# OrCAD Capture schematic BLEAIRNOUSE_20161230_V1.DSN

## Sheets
1 4:BLE_RF: size A
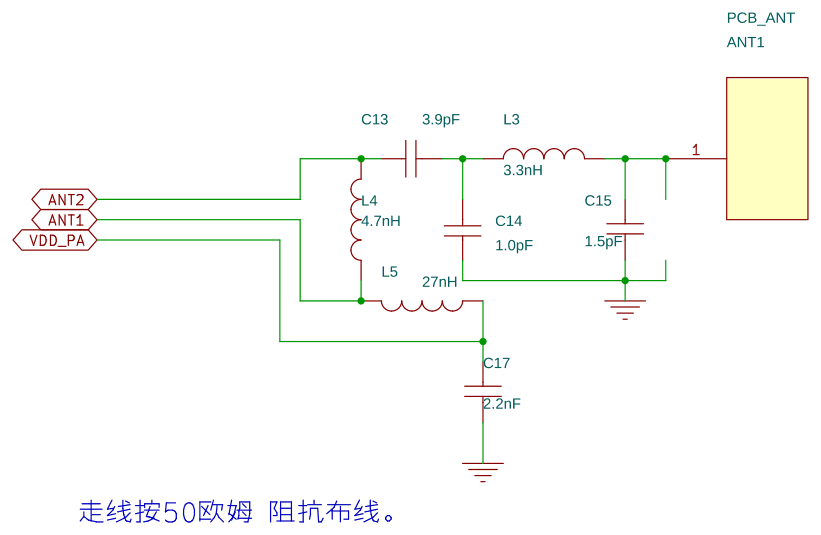
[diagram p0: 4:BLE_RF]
2 3:MISC: size A
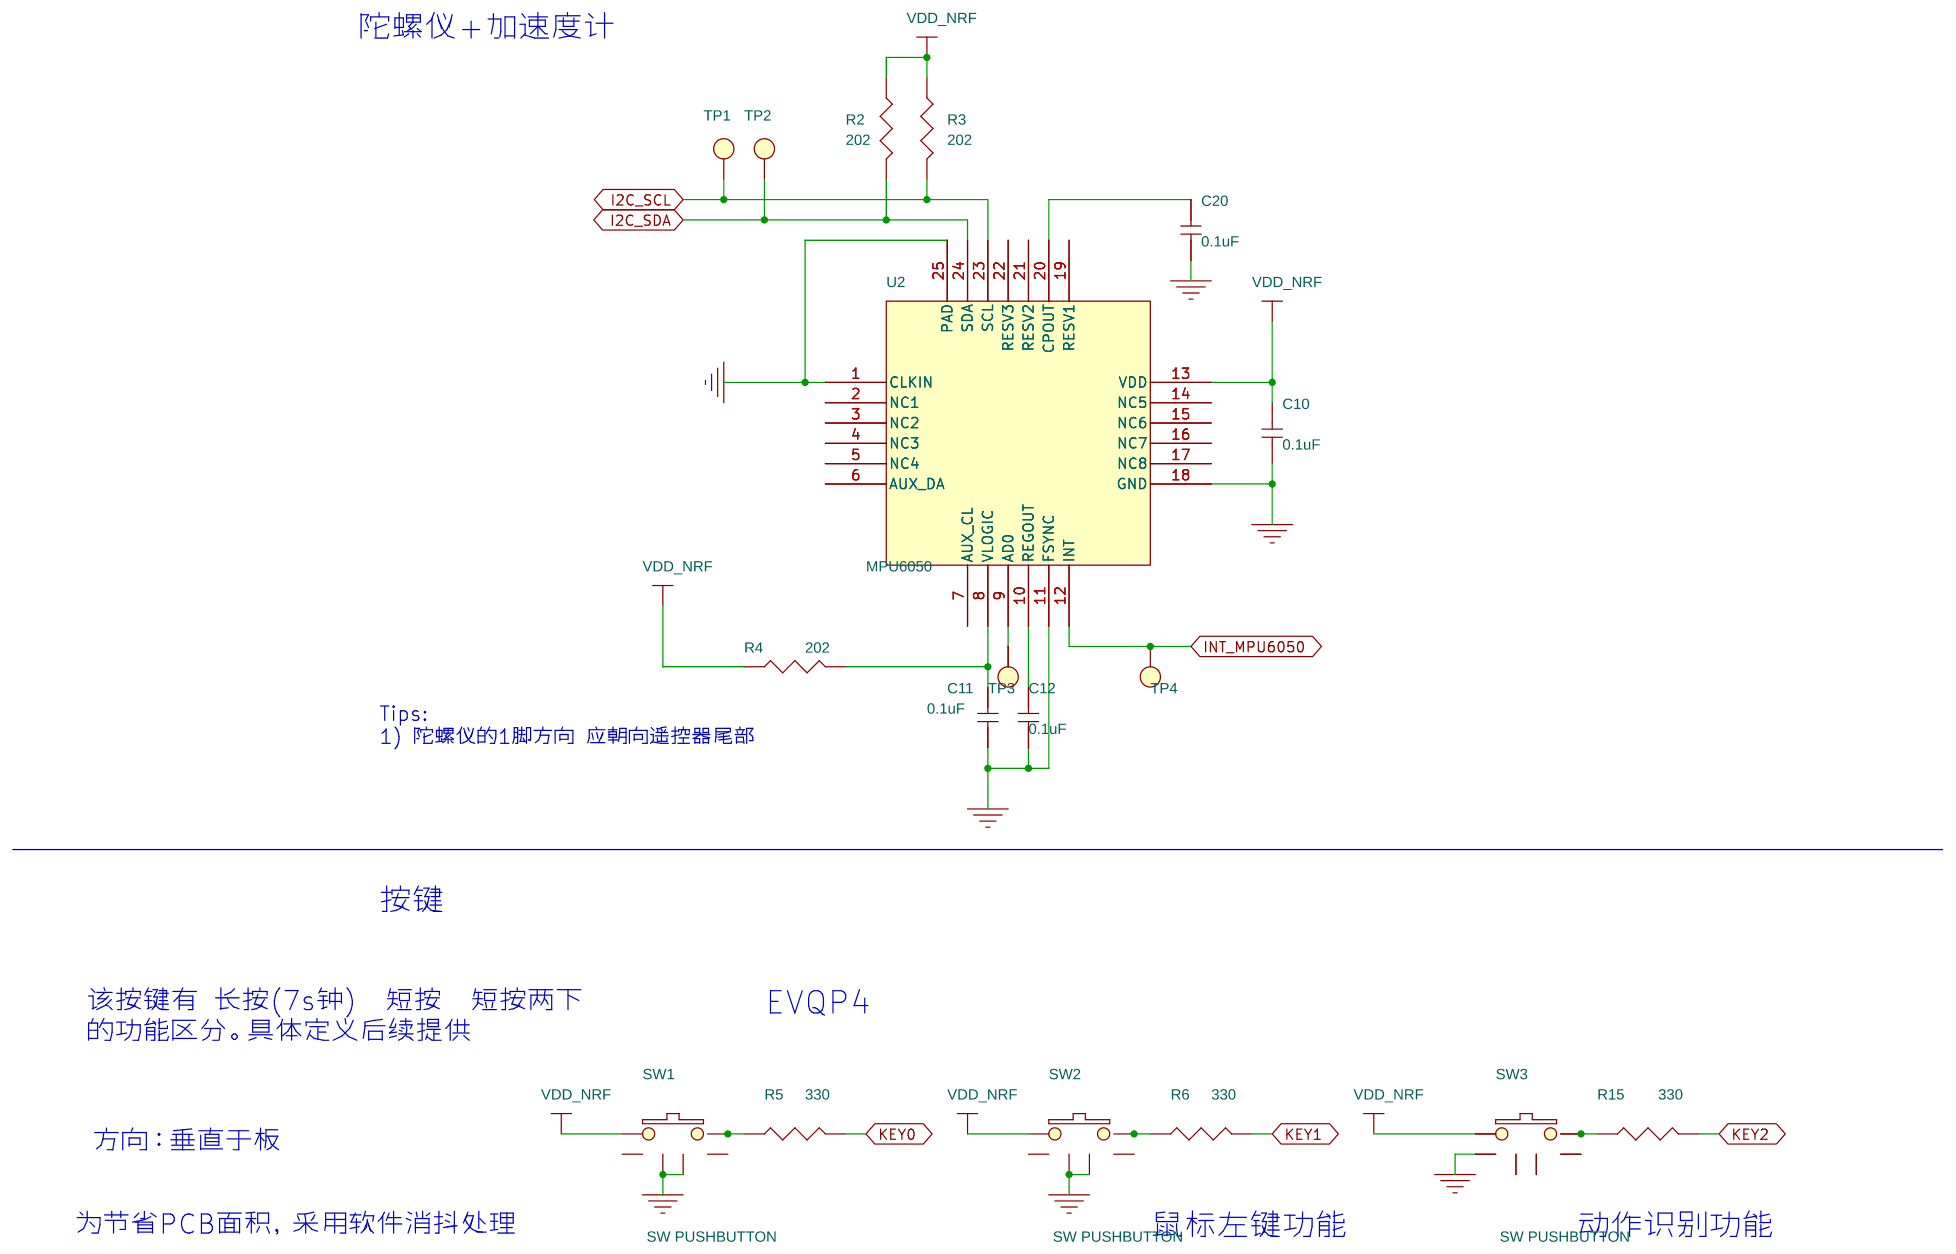
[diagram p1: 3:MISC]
3 2:nrf51822: size A
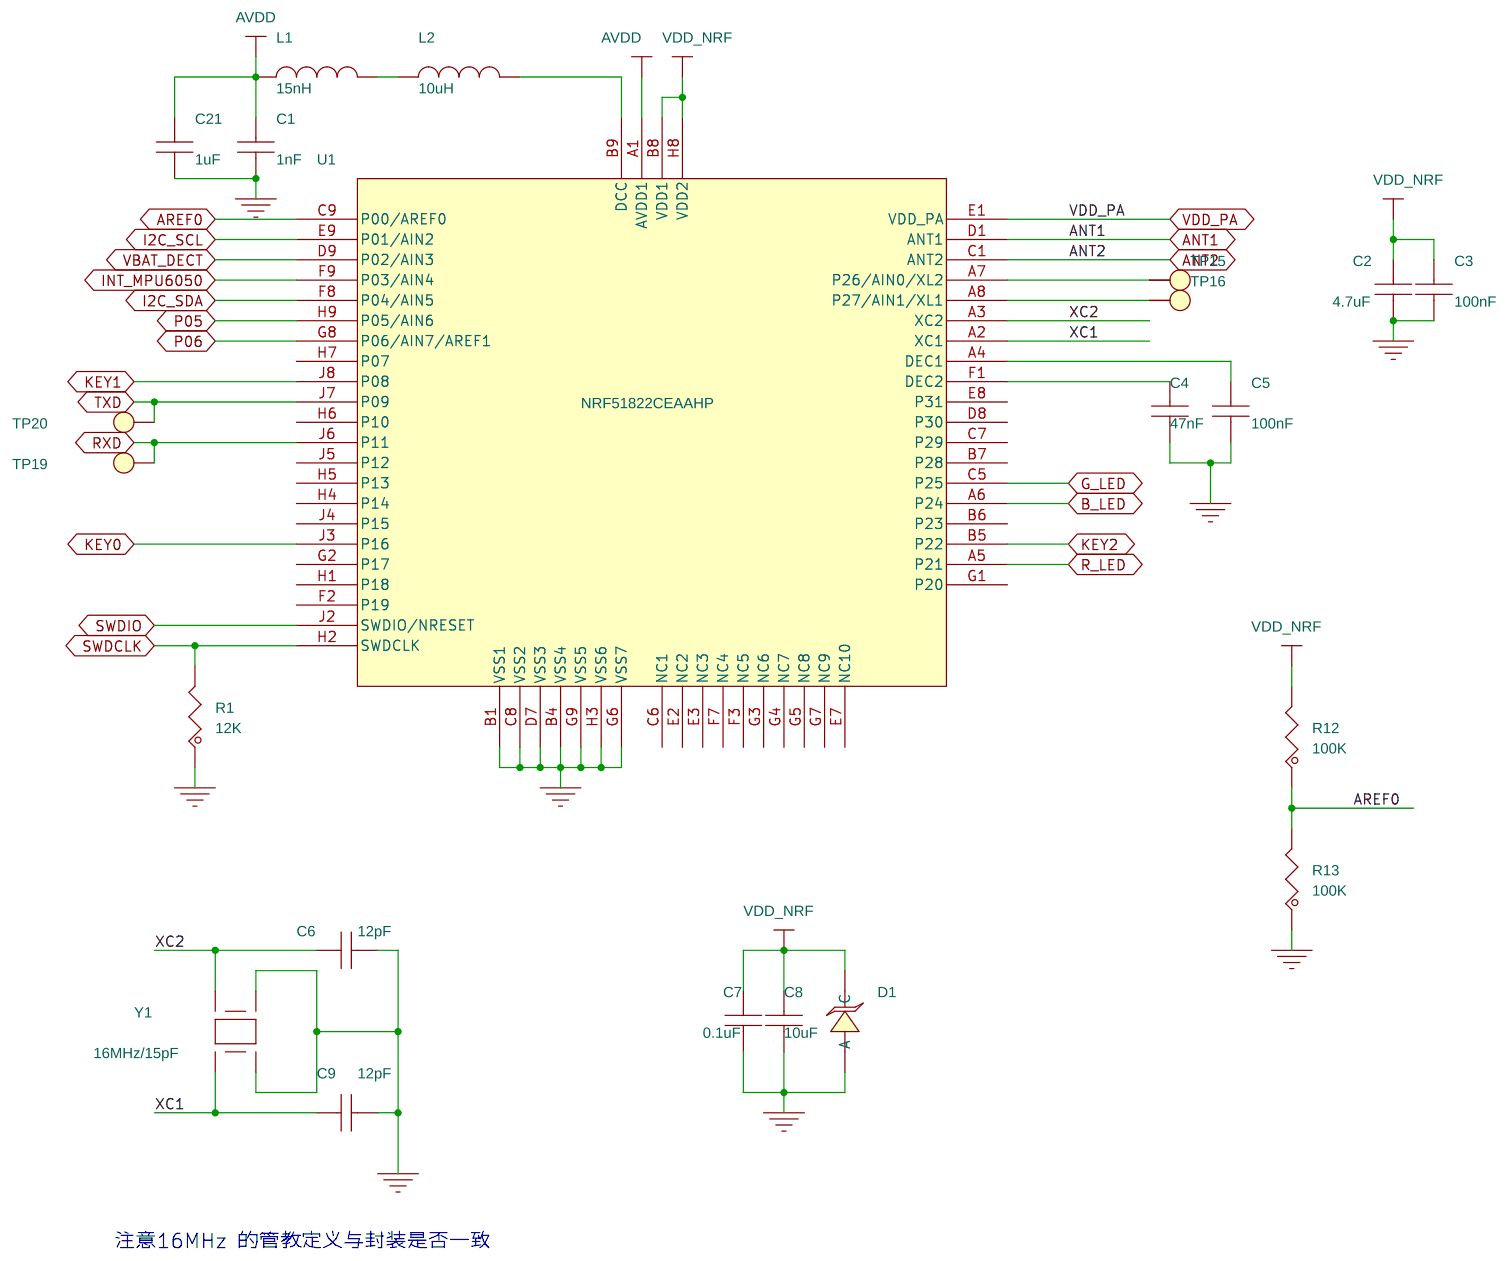
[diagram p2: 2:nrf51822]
4 1:VERSION
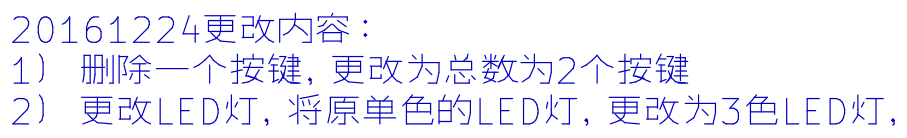
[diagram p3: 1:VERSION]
5 5:Interface: size A
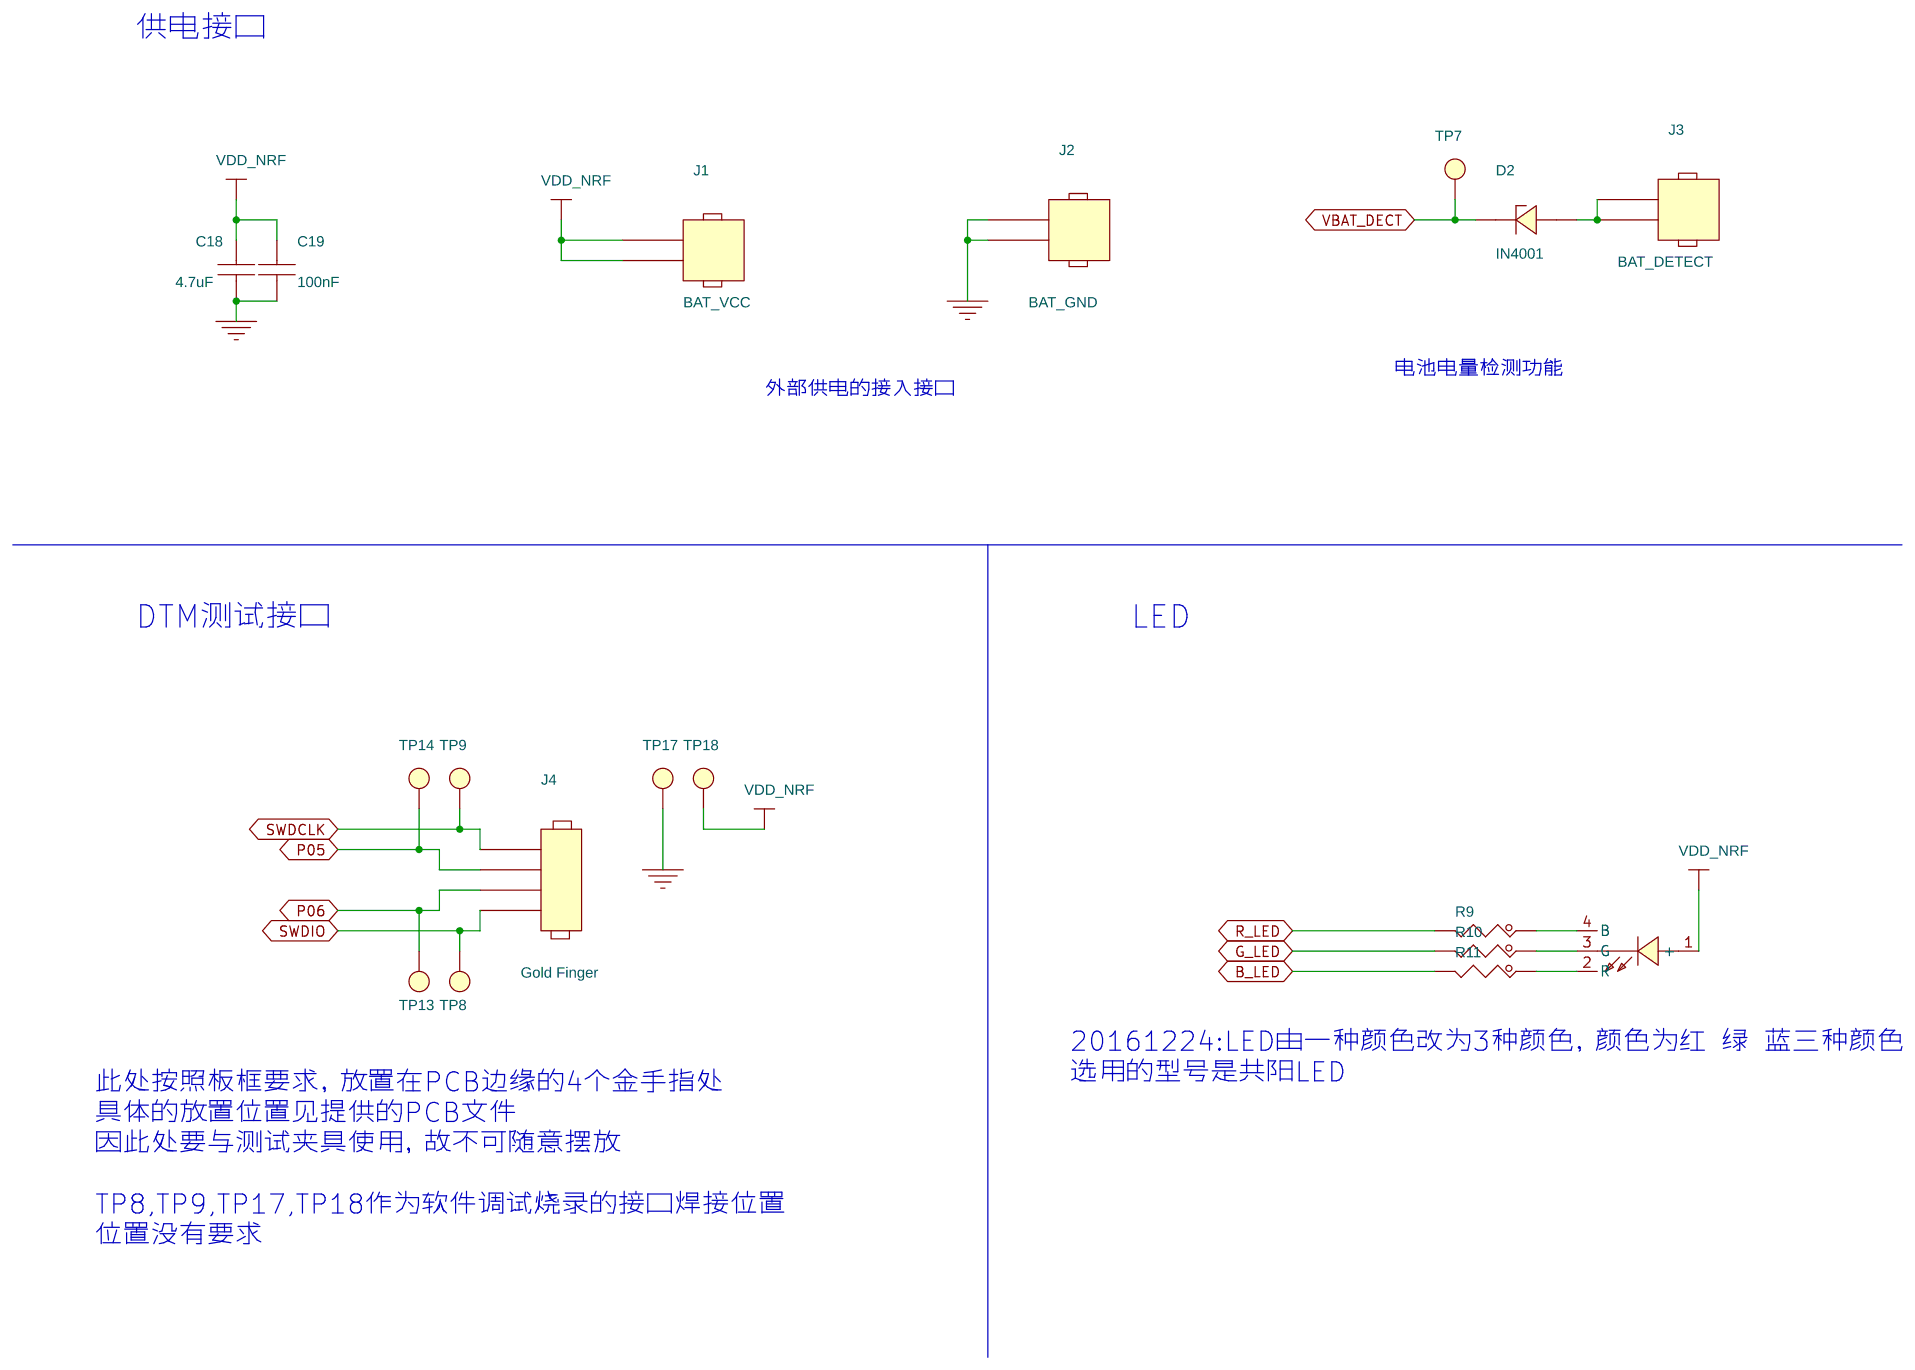
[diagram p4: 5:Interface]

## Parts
sheet 2:nrf51822
C1  1nF  [C0402]
C2  4.7uF  [C0402]
C3  100nF  [C0402]
C4  47nF  [C0402]
C5  100nF  [C0402]
C6  12pF  [C0402]
C7  0.1uF  [C0402]
C8  10uF  [C0402]
C9  12pF  [C0402]
C21  1uF  [C0402]
D1  ESD9L5.0ST5G  [SOD723]
L1  15nH  [L0402]
L2  10uH  [L0603]
R1  12K  [R0402]
R12  100K  [R0402]
R13  100K  [R0402]
TP15  TP_35MIL  [TP-1MM]
TP16  TP_35MIL  [TP-1MM]
TP19  TP_35MIL  [TP-1MM]
TP20  TP_35MIL  [TP-1MM]
U1  NRF51822CEAAHP  [NRF51822WLCSP]
Y1  16MHz/15pF  [X2520]
sheet 3:MISC
C10  0.1uF  [C0402]
C11  0.1uF  [C0402]
C12  0.1uF  [C0402]
C20  0.1uF  [C0402]
R2  202  [R0402]
R3  202  [R0402]
R4  202  [R0402]
R5  330  [R0402]
R6  330  [R0402]
R15  330  [R0402]
SW1  SW PUSHBUTTON  [SW-3_5X2_7-SMD]
SW2  SW PUSHBUTTON  [SW-3_5X2_7-SMD]
SW3  SW PUSHBUTTON  [EVQP4]
TP1  TP_35MIL  [TP-1MM]
TP2  TP_35MIL  [TP-1MM]
TP3  TP_35MIL  [TP-1MM]
TP4  TP_35MIL  [TP-1MM]
U2  MPU6050  [QFN24-4X4]
sheet 4:BLE_RF
ANT1  PCB_ANT  [ANT_3]
C13  3.9pF  [C0402]
C14  1.0pF  [C0402]
C15  1.5pF  [C0402]
C17  2.2nF  [C0402]
L3  3.3nH  [L0402]
L4  4.7nH  [L0402]
L5  27nH  [L0402]
sheet 5:Interface
C18  4.7uF  [C0402]
C19  100nF  [C0402]
D2  IN4001  [SOD723]
J1  BAT_VCC  [BAT-JC]
J2  BAT_GND  [BAT-]
J3  BAT_DETECT  [BAT-JC]
J4  Gold Finger  [DIP4-2_0A]
R9  1k  [R0402]
R10  1k  [R0402]
R11  1k  [R0402]
TP7  TP_35MIL  [TP-1MM]
TP8  TP_35MIL  [TP-1MM]
TP9  TP_35MIL  [TP-1MM]
TP13  TP_35MIL  [TP-1MM]
TP14  TP_35MIL  [TP-1MM]
TP17  TP_35MIL  [TP-1MM]
TP18  TP_35MIL  [TP-1MM]
U3  0603_RGBLED  [LED_RGB_1MMX1MM]

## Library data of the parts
C1-C9 C13-C15 C17-C19 C21 = 10NF_0402_X7R_25V: Descriptions: CAP,X7R,0402,0.01uF,25V,10%; MRVLPN: 6310000-00; Part Number: GRM155R71E103KA01D; Part Type: CAP; Unit_Price($): 0.00065; Vendor: Murata; Vendor_P/N: GRM155R71E103KA01D; Datasheet: D:\Datasheet\MURATA\murata_cap.PDF
D1 = DIODE_TVS_0: DIODE TVS ESD PROT ULT LOW CAP 5-5.4V SOD-923; AGILE_PN: 480-77934; CAD_APPROVED: Yes; HEIGHT: 0.40MM; MFG_NAME01: ON SEMICONDUCTOR; ROHS: Yes
L1-L5 = L0402_2.7NH_ACX
R1 R12 R13 = RES: Descriptions: RES,THK,0402,13.3K,1%,63mW; MRVLPN: 6360070-00; Part Number: RC0402FR-0713K3L; Part Type: Resistor; Vendor: YAGEO; Vendor_P/N: RC0402FR-0713K3L
TP1-TP4 TP7-TP9 TP13-TP20 = T_POINT_R: TEST POINT PAD .035 SMT, no part to order; AGILE_PN: 510-75618; CAD_APPROVED: Yes; HEIGHT: 0.1MM; ROHS: Yes
U1 = NRF51822CEAAHP
Y1 = CRYSTAL_DIP_0: Descriptions: TXC,DIP HC-49S 9B SERIES,12MHz/18pF,30PPM,Fundamental; MRVLPN: 6350020-00; Part Number: 12MHz/18pF; Vendor: TXC; Vendor_P/N: 12MHz_18pF
C10-C12 C20 = C
R2-R6 R15 = 240R_0402_1%: Descriptions: RES,THK,0402,240,1%,63mW; MRVLPN: 6360025-00; Part Number: RC0402FR-07240RL; Part Type: Resistor; Unit_Price($): 0.0004; Vendor: YAGEO; Vendor_P/N: RC0402FR-07240RL
SW1 = SW_PUSHBUTTON_1
SW2 SW3 = SW_PUSHBUTTON_2
U2 = MPU6050
ANT1 = Antenna_0: Descriptions: PCB ANTENNA, FOR 2.4GHz & 5GHz Band; MRVLPN: 6350050-00
D2 = DIODE_BREAKDOWN_4
J1-J3 = HEADER_2
J4 = 4_HEADER
R9-R11 = RES: RES MF 10.0K 1/16W 1% AEC-Q200 0402; AGILE_PN: 470-75416; CAD_APPROVED: Yes; FPLIST: RC0402_25,RC0402_HD,0402_CC; MFG_NAME01: KOA SPEER; MFG_PN01: RK73H1ETTP1002F; ROHS: Yes; SIGNAL_MODEL: DEFAULT_RESISTOR_10000OHM_2_1; Tolerance: 1%
U3 = 0603_RGBLED

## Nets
AVDD: C1.1 C21.1 L1.2 U1.A1(AVDD1)
GND: C1.2 C2.2 C3.2 C4.2 C5.2 C6.2 C7.2 C8.2 C9.2 C10.2 C11.2 C12.2 C14.1 C15.2 C17.2 C18.2 C19.2 C20.2 C21.2 D1.1(A) J2.1 J2.2 R1.1 R13.1 SW1.5 SW1.6 SW2.5 SW2.6 SW3.3 TP17.1(TP) U1.B1(VSS1) U1.B4(VSS4) U1.C8(VSS2) U1.D7(VSS3) U1.G6(VSS7) U1.G9(VSS5) U1.H3(VSS6) U2.1(CLKIN) U2.11(FSYNC) U2.18(GND) U2.25(PAD) Y1.2 Y1.4
VBAT_DECT: D2.2(CATHODE) TP7.1(TP) U1.D9(P02/AIN3)
VDD_nRF: C2.1 C3.1 C7.1 C8.1 C10.1 C18.1 C19.1 D1.2(C) J1.1 J1.2 R2.1 R3.1 R4.1 R12.2 SW1.2 SW2.2 SW3.2 TP18.1(TP) U1.B8(VDD1) U1.H8(VDD2) U2.13(VDD) U3.1(+)
VDD_PA: C17.1 L5.1 U1.E1(VDD_PA)
ANT1: L4.1 L5.2 U1.D1(ANT1)
ANT2: C13.1 L4.2 U1.C1(ANT2)
AREF0: R12.1 R13.2 U1.C9(P00/AREF0)
B_LED: R11.2 U1.A6(P24)
G_LED: R10.2 U1.C5(P25)
I2C_SCL: R3.2 TP1.1(TP) U1.E9(P01/AIN2) U2.23(SCL)
I2C_SDA: R2.2 TP2.1(TP) U1.F8(P04/AIN5) U2.24(SDA)
INT_MPU6050: TP4.1(TP) U1.F9(P03/AIN4) U2.12(INT)
KEY0: R5.2 U1.J3(P16)
KEY1: R6.2 U1.J8(P08)
KEY2: R15.2 U1.B5(P22)
P05: J4.3 TP14.1(TP) U1.H9(P05/AIN6)
P06: J4.2 TP13.1(TP) U1.G8(P06/AIN7/AREF1)
R_LED: R9.2 U1.A5(P21)
RXD: TP19.1(TP) U1.J6(P11)
SWDCLK: J4.4 R1.2 TP9.1(TP) U1.H2(SWDCLK)
SWDIO: J4.1 TP8.1(TP) U1.J2(SWDIO/NRESET)
TXD: TP20.1(TP) U1.J7(P09)
XC1: C9.1 U1.A2(XC1) Y1.3(sig2)
XC2: C6.1 U1.A3(XC2) Y1.1(sig1)
N756550: C11.1 R4.2 U2.8(VLOGIC)
N756642: C12.1 U2.10(REGOUT)
N761008: R6.1 SW2.1
N770152: TP3.1(TP) U2.9(AD0)
N772398: C4.1 U1.F1(DEC2)
N772402: C5.1 U1.A4(DEC1)
N772486: TP16.1(TP) U1.A8(P27/AIN1/XL1)
N774070: L1.1 L2.2
N774429: L2.1 U1.B9(DCC)
N780506: D2.1 J3.1 J3.2
N781791: R9.1 U3.4(B)
N786255: ANT1.1 C15.1 L3.1
N786271: C13.2 C14.2 L3.2
N793028: R10.1 U3.3(G)
N793032: R11.1 U3.2(R)
N795092: TP15.1(TP) U1.A7(P26/AIN0/XL2)
N796039: C20.1 U2.20(CPOUT)
N798278: R15.1 SW3.1
N800618: R5.1 SW1.1

Not connected (* = marked no-connect by the designer): SW1 3 4; SW2 3 4; SW3 4 5 6; U1 B6(P23) B7(P28) C6(NC1) C7(P29) D8(P30) E2(NC2) E3(NC3) E7(NC10) E8(P31) F2(P19) F3(NC5) F7(NC4) G1(P20) G2(P17) G3(NC6) G4(NC7) G5(NC8) G7(NC9) H1(P18) H4(P14) H5(P13) H6(P10) H7(P07) J4(P15) J5(P12); U2 2(NC1) 3(NC2) 4(NC3) 5(NC4) 6(AUX_DA) 7(AUX_CL) 14(NC5) 15(NC6) 16(NC7) 17(NC8) 19(RESV1) 21(RESV2) 22(RESV3)

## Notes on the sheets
sheet 1
- 走线按50欧姆 阻抗布线。
sheet 2
- 陀螺仪+加速度计
- Tips:
  1) 陀螺仪的1脚方向 应朝向遥控器尾部
- 按键
- 该按键有 长按(7s钟)  短按  短按两下
  的功能区分。具体定义后续提供
- EVQP4
- 方向：垂直于板
- 为节省PCB面积，采用软件消抖处理
- 鼠标左键功能
- 动作识别功能
sheet 3
- 注意16MHz 的管教定义与封装是否一致
sheet 4
- 20161224更改内容：
  1） 删除一个按键，更改为总数为2个按键
  2） 更改LED灯，将原单色的LED灯，更改为3色LED灯，
sheet 5
- 供电接口
- 电池电量检测功能
- 外部供电的接入接口
- DTM测试接口
- LED
- 20161224:LED由一种颜色改为3种颜色，颜色为红 绿 蓝三种颜色
  选用的型号是共阳LED
- 此处按照板框要求，放置在PCB边缘的4个金手指处
  具体的放置位置见提供的PCB文件
- 因此处要与测试夹具使用，故不可随意摆放
  TP8,TP9,TP17,TP18作为软件调试烧录的接口焊接位置
  位置没有要求
